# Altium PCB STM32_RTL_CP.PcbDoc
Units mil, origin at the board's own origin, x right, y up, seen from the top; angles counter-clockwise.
Board outline 3165.87 x 3946.73 mil, 2 copper layers (Top Layer, Bottom Layer); 80 components, 87 nets, 425 pads, 181 vias.
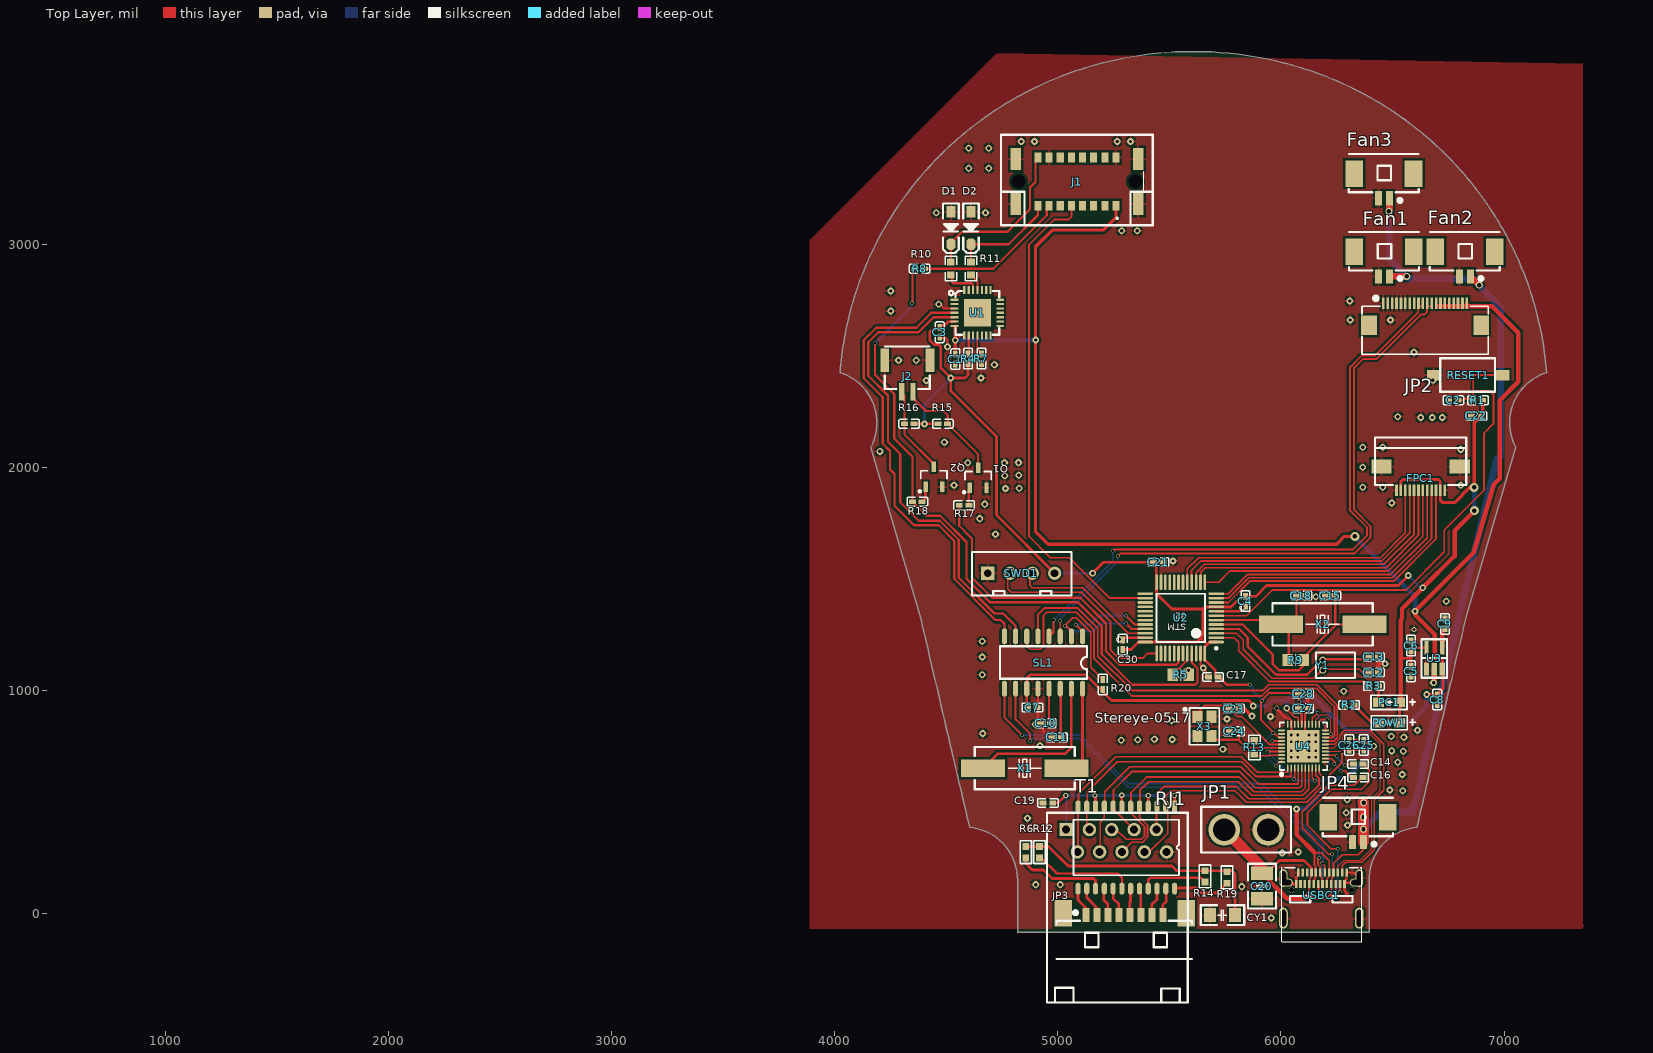
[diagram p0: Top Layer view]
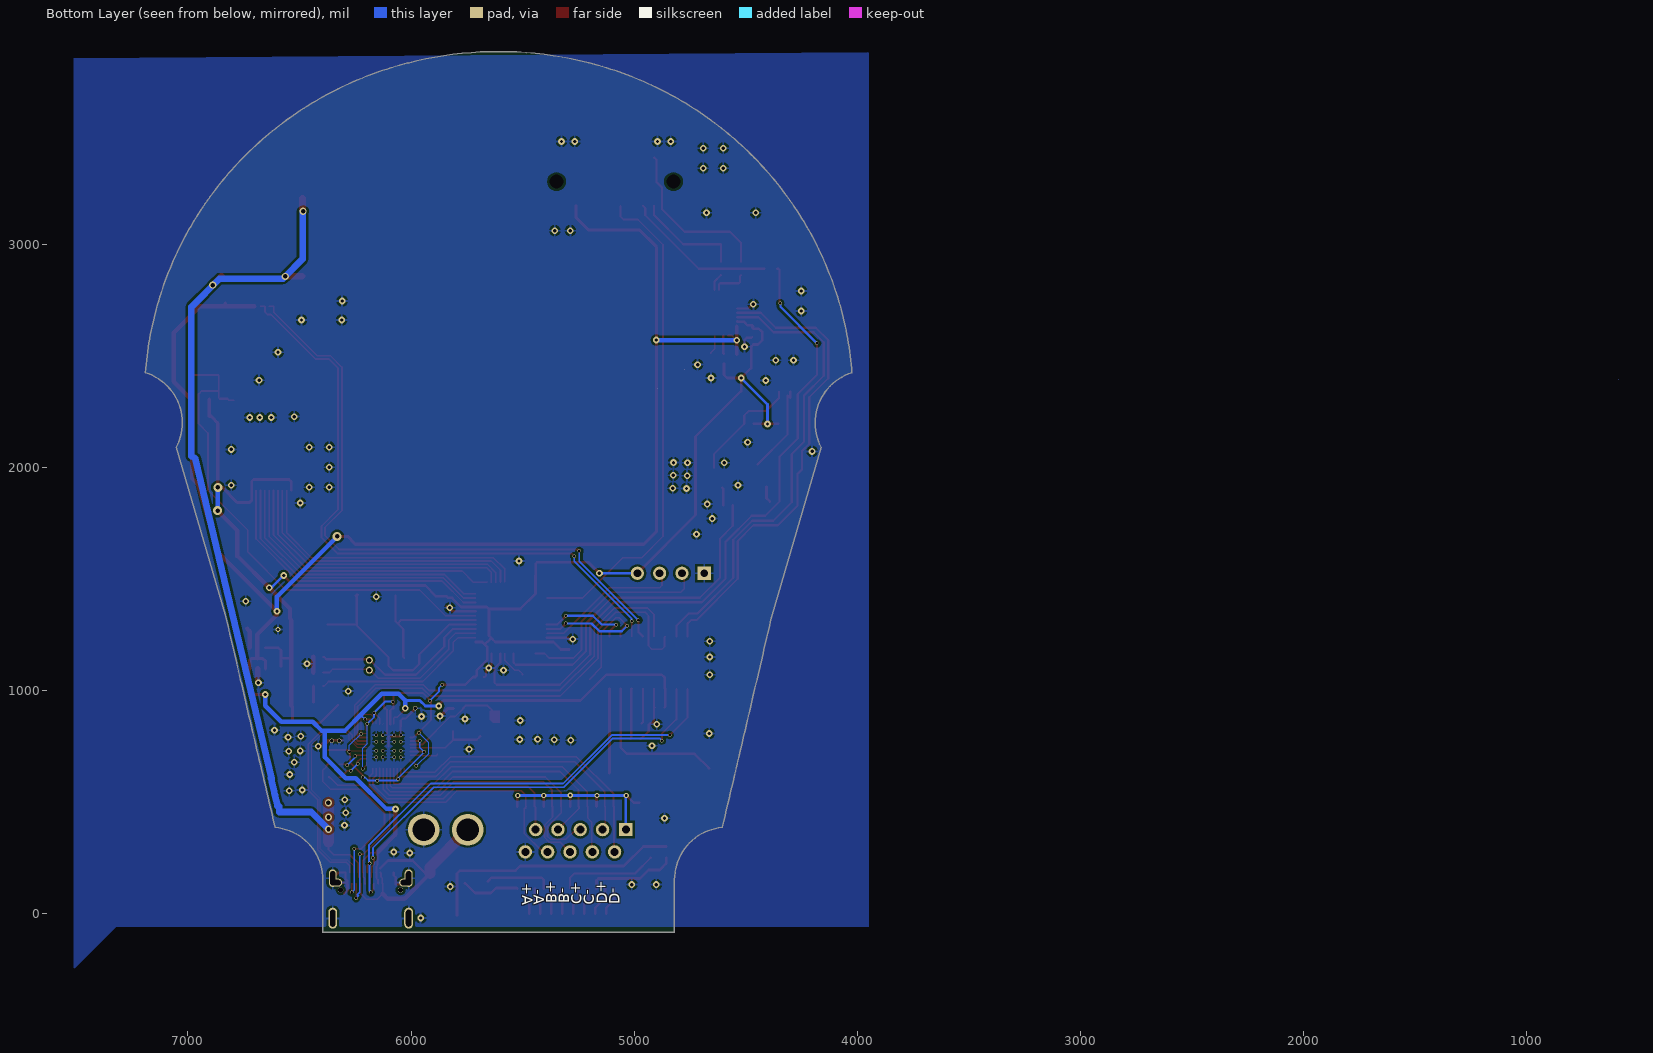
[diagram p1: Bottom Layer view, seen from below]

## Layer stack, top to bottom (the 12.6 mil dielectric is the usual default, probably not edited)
Top Solder: solder mask 0.4, Solder Resist, Dk 3.5
Top Layer: signal copper 1.4
Dielectric 1: dielectric 12.6, FR-4, Dk 4.8
Bottom Layer: signal copper 1.4
Bottom Solder: solder mask 0.4, Solder Resist, Dk 3.5

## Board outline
890 vertices, not listed, extent 4024.3,-84.27 7190.16,3862.46
cut-out: 4894,2351
cut-out: 4774,2440

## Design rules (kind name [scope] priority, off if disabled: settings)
Clearance [All] p1: gap=5 ignorepadtopadclearanceinfootprint=FALSE except(10: Arc-Fill Arc-Poly Arc-Region Track-Fill Track-Poly Track-Region SMDPad-Fill SMDPad-Poly SMDPad-Region THPad-Fill THPad-Poly THPad-Region Via-Fill Via-Poly Via-Region Fill-Fill Fill-Poly Fill-Region Poly-Poly Poly-Region Region-Region)
DiffPairsRouting [All] p1: maxlimit=50 minlimit=5 mostfreqgap=5 toplayer_minwidth=5 toplayer_maxwidth=20 toplayer_prefwidth=8 bottomlayer_minwidth=5 bottomlayer_maxwidth=20 bottomlayer_prefwidth=8 maxuncoupledlength=500
PolygonConnect [All] p1: connectstyle=Relief reliefconductorwidth=10 reliefentries=4 polygonreliefangle="90 Angle" airgapwidth=10
RoutingVias [All] p1: holewidth=11.81 width=15.75 viastyle="Through Hole" minholewidth=11.81 minwidth=15.75 maxholewidth=28 maxwidth=50
SolderMaskExpansion [All] p1: expansion=4
Width All [All] p1: maxlimit=100 minlimit=5 preferedwidth=10 minimp=50.000000 maximp=50.000000 favimp=50.000000
Width VCC [InNet('5V')] p2: maxlimit=100 minlimit=5 preferedwidth=10
29 further rules are at their usual default settings.

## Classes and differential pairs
differential pair SSTX: +SSTX_P -SSTX_N
differential pair MDI3: +MDI3_P -MDI3_N
differential pair MDI2: +MDI2_P -MDI2_N
differential pair MDI1: +MDI1_P -MDI1_N
differential pair MDI0: +MDI0_P -MDI0_N
differential pair SSRX: +SSRX_P -SSRX_N
differential pair USB3-D: +USB3-D_P -USB3-D_N
differential pair D3: +D3_P -D3_N
differential pair D2: +D2_P -D2_N
differential pair D1: +D1_P -D1_N

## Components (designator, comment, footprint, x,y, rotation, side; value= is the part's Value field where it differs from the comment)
C1 "10UF" C0402_NEW 4541,2485 r270 top
C2 "105" C0402_NEW 6772.54,2300.36 r0 top
C3 "10UF" C0402_NEW 4471,2605 r90 top
C4 "104" C0402_NEW 5841,1400 r90 top
C5 "106" C0402_NEW 6583,1086 r270 top
C6 "104" C0402_NEW 6583,1201 r270 top
C7 "104" C0402_NEW 4886,923 r180 top
C8 "105" C0402_NEW 6700,959 r90 top
C9 "223" C0402_NEW 6735,1298 r270 top
C10 "10uF" C0402_NEW 4946,853 r0 top
C11 "10uF" C0402_NEW 4996,790.08 r0 top
C12 "22P" C0402_NEW 6416,1080 r0 top
C13 "22P" C0402_NEW 6416,1150 r0 top
C14 "0.1uF" C0402_NEW 6346,670 r0 top
C15 "22P" C0402_NEW 6221,1425 r180 top
C16 "0.1uF" C0402_NEW 6346,610 r0 top
C17 "10nf" C0402_NEW 5696,1060 r0 top
C18 "22P" C0402_NEW 6091,1425 r0 top
C19 "0.1UF" C0402_NEW 4956,496 r180 top
C20 "104" "C 1210_L" 5915,123 r90 top
C21 "105" C0402_NEW 5451,1575 r180 top
C22 "105" C0402_NEW 6876,2230 r0 top
C23 "30PF" C0402_NEW 5789,919 r0 top
C24 "30PF" C0402_NEW 5790,817 r0 top
C25 "10nf" C0402_NEW 6371,755 r270 top
C26 "0.1uf" C0402_NEW 6306,755 r270 top
C27 "10nf" C0402_NEW 6099.54,920 r180 top
C28 "0.1uf" C0402_NEW 6099.54,985 r180 top
C30 "10nf" C0402_NEW 5291,1205 r270 top
CY1 "10nF/1KV" "C 1206_L" 5737,-7 r0 top
D1 "FFM107" SOD-123F 4521,3072.17 r270 top
D2 "FFM107" SOD-123F 4611,3072.17 r270 top
Fan1 "HDR-1X2" "MX 1.25-WS-2P" 6462,2966 r180 top
Fan2 "HDR-1X2" "MX 1.25-WS-2P" 6824,2966 r180 top
Fan3 "HDR-1X2" "MX 1.25-WS-2P" 6461,3316 r180 top
FPC1 "FPC-12P" FPC-0.5MM-12P 6626,1950 r0 top
J1 "254587" MH-16 5086,3280 r180 top
J2 "GH1.25_2P" GH1.25_2P 4326,2437.99 r180 top
JP1 "HDR-1X2" XT30 5844.43,376 r0 top
JP2 "HDR-1X20" "FPC0.5 2H-WS-20P" 6646,2636.95 r0 top
JP3 "HDR-1X8" "MX 1.25-WS-8P" 5300,-116 r0 top
JP4 "HDR-1X2" "MX 1.25-WS-2P" 6345,431 r180 top
PC1 "LEDgreen" LED 6484.24,946.5 r0 top
POW1 "LEDred" LED 6485,855 r0 top
Q1 "SI2302" SOT23-3N 4643,1953 r0 top
Q2 "SI2302" SOT23-3N 4445,1957 r0 top
R1 "10K,0603" C0402_NEW 6882.54,2300.36 r0 top
R2 "510R,0603" C0402_NEW 6306,935 r180 top
R3 "510R,0603" C0402_NEW 6416,1020 r180 top
R4 "5k" C0402_NEW 4598,2486.54 r270 top
R5 "10K,0603" 6-0805_N 5551,1070 r0 top
R6 "1K" "R 0603_L" 4857,275 r270 top
R7 "5k" C0402_NEW 4658,2486.54 r270 top
R8 "5k" C0402_NEW 4381,2890 r180 top
R9 "1M" 6-0805_N 6066,1136.13 r0 top
R10 "68R,0603" R0603_NEW 4521,2890.35 r270 top
R11 "68R,0603" R0603_NEW 4611,2890.35 r270 top
R12 "1K" "R 0603_L" 4918,275 r270 top
R13 "2.49k" R0603_NEW 5881,745 r90 top
R14 "1K" "R 0603_L" 5660,167 r270 top
R15 "510R,0603" C0402_NEW 4485,2195 r180 top
R16 "510R,0603" C0402_NEW 4334,2195 r0 top
R17 "68R,0603" C0402_NEW 4580,1830 r180 top
R18 "68R,0603" C0402_NEW 4371,1846 r180 top
R19 "1K" "R 0603_L" 5758,162 r270 top
R20 "5k" C0402_NEW 5202,1026.54 r90 top
RESET1 "SW-PB" Key 6684,2413 r180 top
RJ1 "HR911130A" "RJ45-TH_HR911130A - duplicate" 5267,104 r180 top
SL1 "SL2.1A" SOP-16_L10.0-W3.9-P1.27-LS6.0-BL 4936,1125 r180 top
SWD1 "SWD" HDR1X4H 4686,1525 r0 top
T1 "SG24002g" SG24002 5523.48,480 r270 top
U1 "CP2102" CP2102-28G 4640,2692 r0 top
U2 "STM32F103C8T6" STM32-48P 5551,1325 r180 top
U3 "RT9193-33GB" SOT-23-5 6687.57,1143.76 r0 top
U4 "RTL8153B-VB-CG" QFN-40_L5.0-W5.0-P0.40-BL-EP3.7 6101,750 r0 top
USBC1 "TypeC SMD" USB-C-SMD_MC-312D-C 6181,39.69 r0 top
X1 "12MHz" "OSC HC-49SMD" 4852,652 r180 top
X2 "8MHz" "OSC HC-49SMD" 6187.01,1296 r0 top
X3 "25MHz" OSC-SMD_4P-L3.2-W2.5-BL 5657,839 r90 top
Y1 "32.768K" XLAT-32 6186.98,1135.5 r270 top

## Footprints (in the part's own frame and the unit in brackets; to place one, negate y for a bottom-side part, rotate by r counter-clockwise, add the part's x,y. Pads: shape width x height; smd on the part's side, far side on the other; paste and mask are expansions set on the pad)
6-0805_N [mm] "Chip Resistor, Body 2.0x1.2mm, IPC Medium Density"
  rect 1.2x1.4 smd: 1(-0.9,0) 2(0.9,0)
  silkscreen extent 0,-0.6 0,0.6, body extent -1.07,-0.7 1.07,0.7, height 0.7
C0402_NEW [mm]
  rect 0.79x0.54 smd: 1(-0.545,0) 2(0.545,0)
  silkscreen extent -1.17,-0.5 1.17,0.5
"C 1206_L" [mil] "无极性贴片电容"
  rect 55x62 smd: 1(-55.12,0) 2(57.09,0)
  silkscreen extent -96,-44 98,44, body extent -63,-32 63,32, height 48
"C 1210_L" [mil] "无极性贴片电容                                淘宝ID:黄晶宝石"
  rect 60x100 smd: 1(-57.09,0) 2(57.09,0)
  silkscreen extent -100,-63 100,63, body extent -63,-51 63,51, height 60
CP2102-28G [mil]
  rect 35.4x10 smd: 1(-102,59) 2(-102,39) 3(-102,20) 4(-102,0) 5(-102,-20) 6(-102,-39) 7(-102,-59) 15(102,-59) 16(102,-39) 17(102,-20) 18(102,0) 19(102,20) 20(102,39) 21(102,59)
  rect 10x35.4 smd: 8(-59,-102) 9(-39,-102) 10(-20,-102) 11(0,-102) 12(20,-102) 13(39,-102) 14(59,-102) 22(59,102) 23(39,102) 24(20,102) 25(0,102) 26(-20,102) 27(-39,102) 28(-59,102)
  rect 122x122 smd: 29(0,0)
  silkscreen extent -128,-98 98,99
"FPC0.5 2H-WS-20P" [mm] "长：14.2mm，宽：5.2mm，高：2mm  淘宝ID:黄晶宝石   店铺网址:https://shop463601444.taobao.com"
  rect 1.8x2.2 smd: 0(-6.4,0) 0(6.4,0)
  rect 0.3x1.3 smd: 1(-4.75,2.497) 2(-4.25,2.497) 3(-3.75,2.497) 4(-3.25,2.497) 5(-2.75,2.497) 6(-2.25,2.497) 7(-1.75,2.497) 8(-1.25,2.497) 9(-0.75,2.497) 10(-0.25,2.497) 11(0.25,2.497) 12(0.75,2.497) 13(1.25,2.497) 14(1.75,2.497) 15(2.25,2.497) 16(2.75,2.497) 17(3.25,2.497) 18(3.75,2.497) 19(4.25,2.497) 20(4.75,2.497)
  silkscreen extent -7.18,-3.3 7.18,3.23, body extent -7.1,-3.15 7.1,2.85, height 2
FPC-0.5MM-12P [mm]
  rect 0.3x1.3 smd: 1(-2.751,-1.341) 2(-2.252,-1.341) 3(-1.751,-1.341) 4(-1.251,-1.341) 5(-0.751,-1.341) 6(-0.25,-1.341) 7(0.25,-1.341) 8(0.749,-1.341) 9(1.248,-1.341) 10(1.749,-1.341) 11(2.249,-1.341) 12(2.75,-1.341)
  rect 2.286x1.6 smd: 13(4.45,1.34) 14(-4.45,1.34)
  silkscreen extent -5.18,-0.76 5.18,4.67
GH1.25_2P [mm]
  rect 0.6x2 smd: 1(-0.635,2.54) 2(0.635,2.54)
  rect 1x2.7 smd: 3(2.585,-1.041) 4(-2.565,-1.041)
  silkscreen extent -2.55,-2.62 2.57,2.21
HDR1X4H [mm] "Connector; Header; 4 Position; Right Angle"
  rect 1.5x1.5 hole 0.9: 1(0,0)
  round 1.5 hole 0.9: 2(2.54,0) 3(5.08,0) 4(7.62,0)
  silkscreen extent -1.78,-2.54 9.52,2.41
Key [mil]
  rect 59.06x47.24 smd: 1(0,0) 2(-310,0)
  silkscreen extent -275,-75 -30,75
LED [mil]
  rect 49x43 smd: 1(46.26,0) 2(-46.26,0)
  silkscreen extent -81,-31 118,31
MH-16 [mm]
  rect 0.8x1.1 smd: A1(4.445,-2.75) A2(3.175,-2.75) A3(1.905,-2.75) A4(0.635,-2.75) A5(-0.635,-2.75) A6(-1.905,-2.75) A7(-3.175,-2.75) A8(-4.445,-2.75) B1(4.445,2.75) B2(3.175,2.75) B3(1.905,2.75) B4(0.635,2.75) B5(-0.635,2.75) B6(-1.905,2.75) B7(-3.175,2.75) B8(-4.445,2.75)
  round 0.8 hole 1.6 unplated: MH1(-6.655,0) MH2(6.655,0)
  rect 1.2x2.5 smd: MP1(-6.955,2.55) MP2(-6.955,-2.55) MP3(6.955,2.55) MP4(6.955,-2.55)
  silkscreen extent -8.64,-5.33 8.64,4.95, body extent -7.62,-3.5 7.62,3.5, height 6.7
"MX 1.25-WS-2P" [mm] "长：7.65mm，宽：4.2mm，高：3.4mm"
  rect 2x3 smd: 0(-3.382,0) 0(3.382,0)
  rect 0.8x1.6 smd: 1(-0.639,2.811) 2(0.611,2.811)
  silkscreen extent -3.98,-2.23 4,3.25, body extent -3.83,-2.1 3.83,3.09, height 3.4
"MX 1.25-WS-8P" [mm] "长：15.15mm，宽：4.2mm，高：3.4mm"
  rect 2x3 smd: 0(-7,3) 0(7,3)
  rect 0.8x1.6 smd: 1(-4.389,2.811) 2(-3.139,2.811) 3(-1.889,2.811) 4(-0.639,2.811) 5(0.611,2.811) 6(1.861,2.811) 7(3.111,2.811) 8(4.361,2.811)
  silkscreen extent -7.77,-2.23 7.67,3.25, body extent -7.57,-2.1 7.57,3.09, height 3.4
"OSC HC-49SMD" [mm] "封装库来自淘宝卖家 ID：黄晶宝石"
  rect 5x2 smd: 1(-4.75,0) 2(4.75,0)
  silkscreen extent -5.7,-2.4 5.7,2.4, body extent -6.5,-2.32 6.5,2.33, height 4.63
OSC-SMD_4P-L3.2-W2.5-BL [mm]
  rect 1.4x1.15 smd: 1(1.059,0.8) 2(-1.1,0.8) 3(-1.1,-0.8) 4(1.1,-0.8)
  Top Layer region: 1.8,0.225 0.762,0.225 0.4,0.604 0.4,1.375 1.8,1.375
  silkscreen extent -2.1,-1.7 2.1,2.35
QFN-40_L5.0-W5.0-P0.40-BL-EP3.7 [mm]
  oval 0.2x0.8 smd: 1(-1.8,-2.499) 2(-1.4,-2.499) 3(-1,-2.499) 4(-0.6,-2.499) 5(-0.2,-2.499) 6(0.2,-2.499) 7(0.6,-2.499) 8(1,-2.499) 9(1.4,-2.499) 10(1.8,-2.499) 21(1.8,2.499) 22(1.4,2.499) 23(1,2.499) 24(0.6,2.499) 25(0.2,2.499) 26(-0.2,2.499) 27(-0.6,2.499) 28(-1,2.499) 29(-1.4,2.499) 30(-1.8,2.499)
  oval 0.8x0.2 smd: 11(2.499,-1.8) 12(2.499,-1.4) 13(2.499,-1) 14(2.499,-0.6) 15(2.499,-0.2) 16(2.499,0.2) 17(2.499,0.6) 18(2.499,1) 19(2.499,1.4) 20(2.499,1.8) 31(-2.499,1.8) 32(-2.499,1.4) 33(-2.499,1) 34(-2.499,0.6) 35(-2.499,0.2) 36(-2.499,-0.2) 37(-2.499,-0.6) 38(-2.499,-1) 39(-2.499,-1.4) 40(-2.499,-1.8)
  rect 3.7x3.7 smd: 41(0,0)
  silkscreen extent -2.7,-3.35 2.7,2.7
R0603_NEW [mil]
  rect 31.75x34.02 smd: 1(-29.65,0) 2(29.66,0)
  silkscreen extent -55,-26 55,26
"R 0603_L" [mil] "1/10W贴片电阻                 淘宝ID:黄晶宝石"
  rect 30x30 smd: 1(-25.59,0) 2(25.59,0)
  silkscreen extent -51,-26 51,26, body extent -31,-16 32,16, height 16
"RJ45-TH_HR911130A - duplicate" [mil]
  rect 60x60 hole 35.83: P1(229.63,-272.62)
  round 60 hole 35.83: P2(179.1,-172.38) P3(125.2,-272.38) P4(79.1,-172.38) P5(25.2,-272.38) P6(-20.9,-172.38) P7(-74.8,-272.38) P8(-120.9,-172.38) P9(-174.8,-272.38) P10(-220.9,-172.38)
  silkscreen extent -315,-347 315,503
SG24002 [mm]
  rect 1.35x0.6 smd: 1(0,0)
  oval 1.35x0.6 smd: 2(0,-1) 3(0,-2) 4(0,-3) 5(0,-4) 6(0,-5) 7(0,-6) 8(0,-7) 9(0,-8) 10(0,-9) 11(0,-10) 12(0,-11) 13(9.35,-11) 14(9.35,-10) 15(9.35,-9) 16(9.35,-8) 17(9.35,-7) 18(9.35,-6) 19(9.35,-5) 20(9.35,-4) 21(9.35,-3) 22(9.35,-2) 23(9.35,-1) 24(9.35,0)
  silkscreen extent 1.51,-11.5 7.84,0.5
SOD-123F [mm] "2.7x1.6X1.1mm（长宽高，不包括引脚）"
  rect 1.3x1 smd: 1(-1.85,0)
  oct 1.3x1 smd: 2(1.85,0)
  silkscreen extent -2.79,-0.89 2.84,0.89, body extent -1.9,-0.8 1.9,0.8, height 1.15
SOP-16_L10.0-W3.9-P1.27-LS6.0-BL [mm]
  oval 0.6x1.8 smd: 1(-4.445,-2.972) 2(-3.175,-2.972) 3(-1.905,-2.972) 4(-0.635,-2.972) 5(0.635,-2.972) 6(1.905,-2.972) 7(3.175,-2.972) 8(4.445,-2.972) 9(4.445,2.972) 10(3.175,2.972) 11(1.905,2.972) 12(0.635,2.972) 13(-0.635,2.972) 14(-1.905,2.972) 15(-3.175,2.972) 16(-4.445,2.972)
  silkscreen extent -4.95,-1.85 4.95,1.85
SOT23-3N [mm] "3x1.3x1mm(长宽高)    封装库来自淘宝卖家 ID：黄晶宝石"
  rect 0.5x1.2 smd: 1(-0.95,-1.143) 2(0.95,-1.143) 3(0,1.143)
  silkscreen extent -1.72,-1.78 1.5,0.7, body extent -1.5,-1.2 1.5,1.2, height 1.05
SOT-23-5 [mm]
  rect 0.6x1.5 smd: 1(-0.9,-1.2) 2(0,-1.2)
  rect 0.63x1.5 smd: 3(0.9,-1.2)
  rect 0.5x1.5 smd: 4(0.9,1.2) 5(-0.9,1.2)
  silkscreen extent -1.47,-2.21 1.43,2.18
STM32-48P [mm]
  oval 1.8x0.3 smd: 1(-4.05,2.75) 2(-4.05,2.25) 3(-4.05,1.75) 4(-4.05,1.25) 5(-4.05,0.75) 6(-4.05,0.25) 7(-4.05,-0.25) 8(-4.05,-0.75) 9(-4.05,-1.25) 10(-4.05,-1.75) 11(-4.05,-2.25) 12(-4.05,-2.75) 25(4.05,-2.75) 26(4.05,-2.25) 27(4.05,-1.75) 28(4.05,-1.25) 29(4.05,-0.75) 30(4.05,-0.25) 31(4.05,0.25) 32(4.05,0.75) 33(4.05,1.25) 34(4.05,1.75) 35(4.05,2.25) 36(4.05,2.75)
  oval 0.3x1.8 smd: 13(-2.75,-4.05) 14(-2.25,-4.05) 15(-1.75,-4.05) 16(-1.25,-4.05) 17(-0.75,-4.05) 18(-0.25,-4.05) 19(0.25,-4.05) 20(0.75,-4.05) 21(1.25,-4.05) 22(1.75,-4.05) 23(2.25,-4.05) 24(2.75,-4.05) 37(2.75,4.05) 38(2.25,4.05) 39(1.75,4.05) 40(1.25,4.05) 41(0.75,4.05) 42(0.25,4.05) 43(-0.25,4.05) 44(-0.75,4.05) 45(-1.25,4.05) 46(-1.75,4.05) 47(-2.25,4.05) 48(-2.75,4.05)
  silkscreen extent -4.18,-2.75 2.75,3.57, body extent -3.5,-3.5 3.5,3.5, height 1.6
USB-C-SMD_MC-312D-C [mm]
  oval 0.9x2 hole 0.6 slot 1.6 at 90 deg: 1(-4.32,3.018) 2(4.32,3.018)
  oval 1.5x0.9 hole 0.6 slot 1.2 at 0 deg: 1(-4,2.518) 2(4,2.518)
  oval 1x2.4 hole 0.6 slot 1.9 at 90 deg: 3(4.32,-1.532) 4(-4.32,-1.532)
  rect 0.3x0.95 smd: A1(-2.62,3.668) A2(-2.12,3.668) A3(-1.62,3.668) A4(-1.12,3.668) A5(-0.62,3.668) A6(-0.12,3.668) A7(0.38,3.668) A8(0.88,3.668) A9(1.38,3.668) A10(1.88,3.668) A11(2.38,3.668) A12(2.88,3.668) B1(2.63,2.368) B2(2.13,2.368) B3(1.63,2.368) B4(1.13,2.368) B5(0.63,2.368) B6(0.13,2.368) B7(-0.37,2.368) B8(-0.87,2.368) B9(-1.37,2.368) B10(-1.87,2.368) B11(-2.37,2.368) B12(-2.87,2.368)
  round 0.6 hole 0.6 unplated: ""(-3.4,1.668) ""(3.4,1.668)
  silkscreen extent -4.57,-4.2 4.57,4.18
XLAT-32 [mm]
  round 0.8 hole 0.5: 0(0,0) 1(1.143,0)
  silkscreen extent -0.89,-0.76 2.03,3.68
XT30 [mm]
  round 3.6 hole 2.6: 1(-2.5,0) 2(2.5,0)
  silkscreen extent -5.12,-2.59 5.09,2.62

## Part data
C1 C3: library part 47uf, BOM_Manufacturer Part=?
C2 C4 C5 C6 C7 C8 C9 C12 C13 C15 C18 C20 C21 C22: BOM_Manufacturer=YAGEO, BOM_Manufacturer Part=CC0603KRX7R9BB104
C10 C11: BOM_JLCPCB Part Class="Extended Part", BOM_Manufacturer=SAMSUNG, BOM_Manufacturer Part=CL10A106MP8NNNC
CY1: library part CY, "安规Y电容"
D1 D2: "快恢复整流二极管"
Fan1 Fan2 Fan3 JP1 JP4: library part "Header 2", "2P接插件"
FPC1: BOM_Manufacturer=JUSHUO, BOM_Manufacturer Part=AFC01-S12FCA-00
J1: "Connector", Manufacturer_Name=ERNI, Mouser Part Number=305-254587
JP2: library part "Header 20", "20P接插件"
JP3: library part "Header 8", "8P接插件"
PC1 POW1: library part LED
Q1 Q2: "N沟道场效应管"
R1 R5: BOM_Manufacturer=UniOhm, BOM_Manufacturer Part=060300J0103T5E
R2 R3 R15 R16: BOM_Manufacturer=UniOhm, BOM_Manufacturer Part=0603WAJ0511T5E
R4 R7 R8 U1: BOM_Manufacturer Part=?
R6 R12 R14 R19: library part R, "贴片电阻"
R9: library part 1M0603, BOM_Manufacturer="Uniroyal Elec", BOM_Manufacturer Part=0603WAF1054T5E
R10 R11 R17 R18 R20: library part 510R,0603, BOM_Manufacturer=UniOhm, BOM_Manufacturer Part=0603WAJ0511T5E
RJ1: BOM_Manufacturer=HANRUN
SL1: BOM_LCSC Assembly=Yes, BOM_Manufacturer=CoreChips
SWD1: BOM_Manufacturer=Ckmtw, BOM_Manufacturer Part="210S-1*4P L{}11.6MMGold-plated black"
U3: BOM_Manufacturer=RICHTEK, ICA_PARTNUM=$$2191094$$RT9193-15CU5, Part Number=TMP-13
U4: BOM_JLCPCB Part Class="Extended Part", BOM_Manufacturer=REALTEK(瑞昱)
X1: BOM_JLCPCB Part Class="Extended Part", BOM_Manufacturer=YXC, BOM_Manufacturer Part=X49SD12MSD2SC
X2: BOM_Manufacturer="ZheJiang East Crystal Elec", BOM_Manufacturer Part=B08000J065
X3: BOM_LCSC Assembly=Yes, BOM_Manufacturer="Zhejiang Abel Elec", BOM_Manufacturer Part=SMD-3225_4P25MHZ12PF10PPM-40~+85℃
Y1: library part XLAT-32, BOM_Manufacturer=KDS, BOM_Manufacturer Part="DST310S 32.768KHz"

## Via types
v1: diameter 30, hole 15, Top Layer to Bottom Layer, 108 vias
v2: diameter 15.75, hole 11.81, Top Layer to Bottom Layer, 55 vias
v3: diameter 32, hole 20, Top Layer to Bottom Layer, 6 vias
v4: diameter 24, hole 12, Top Layer to Bottom Layer, 6 vias
v5: diameter 40, hole 20, Top Layer to Bottom Layer, 3 vias
v6: diameter 20, hole 15.75, Top Layer to Bottom Layer, 3 vias

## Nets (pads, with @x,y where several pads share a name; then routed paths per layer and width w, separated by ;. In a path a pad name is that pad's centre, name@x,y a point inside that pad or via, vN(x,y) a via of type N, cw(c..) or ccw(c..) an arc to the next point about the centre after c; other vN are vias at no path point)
1V0: C25.2 C26.2 U4.3 U4.8 U4.14 U4.19 U4.22 U4.34 U4.37 | length 1229.7
  Top Layer w5: U4.22 6156.67,848.95 6156.67,869.27 6172.02,884.63 6172.37,884.63 6177.74,890 6211,890 6222.65,878.35 v2(6222.65,806.65) 6200.93,806.65 U4.19 ; U4.14 v2@6276,726.38
  Top Layer w8: v2(5941,724.25) 5943.1,724.25 5945.22,726.38 U4.37 ; v2(5961,775) 5962.31,773.69 6002.54,773.69 U4.34 ; v2(6058,602) 6061.63,605.63 U4.3 ; U4.8 6140.43,651.54 6140.43,607.66 6151,597.1 v2(6151,595) ; v2(6216,610) 6216,620 6274.13,678.13 v2@6274.13,723.13 ; v2(6276,725) 6276,726.38 6276,730 6279.54,733.54 C26.2 C25.2
  Bottom Layer w5: v2(6222.65,806.65) 6276,753.3 v2(6276,725)
  Bottom Layer w8: v2(5961,775) 5961,744.25 v2(5941,724.25) 6058.4,606.86 6058.4,597 6193,597 6206,610 v2(6216,610)
3V3: C3.2 C4.2 C5.1 C6.2 C17.2 C21.2 C22.2 C27.2 C28.2 C30.2 FPC1.2 FPC1.11 PC1.1 POW1.1 R1.2 R4.2 R15.2 R16.2 SWD1.4 U1.6 U2.1 U2.9 U2.24 U2.36 U2.48 U3.5 U4.11 U4.20 U4.23 U4.26 U4.33 U4.39 U4.40 | length 8491.5
  Top Layer w5: v2@5976,660 v2(5976,662.17) 5976,664.35 5990.79,679.13 U4.40 U4.39 ; U4.11 6199.4,666.6 v2(6216,650)
  Top Layer w8: U4.33 5990.91,789.37 5988.1,792.18 5985.43,792.18 5911,866.61 5911,953.23 5946.88,989.12 6073.97,989.12 C28.2 ; U4.23 6140.43,848.46 6140.43,874.43 v2(6166,900) ; v2(6196,850) 6199.4,846.6 U4.20
  Top Layer w10: C28.2 C27.2 6083.01,920 6093.13,909.88 U4.26
  Top Layer w12: R16.2 R15.2 ; 4425.97,2595.03 4425.97,2604.97 4442.37,2621.37 4466.37,2621.37 4471,2626 C3.2 ; 4426,2595 4426,2570 4446,2550 4466,2550 4476,2540 4476,2445 v1(4521,2400) ; C3.2@4466,2626.46 4466,2631.38 4470.63,2636.01 4492.01,2636.01 4508,2652 4537,2652 U1.6 ; R4.2 4598,2414.03 4583.97,2400 v1(4521,2400) ; SWD1.4 4725,1786 4725,2137 4521,2341 v1(4521,2400) ; v1(5156,1525) 5206,1575 C21.2 5434.47,1575 5441.1,1568.37 5441.1,1516.64 5442.73,1515.01 U2.24 5442.73,1433.27 5511,1365 5651,1365 ; C30.2 5328.83,1183.54 5362.02,1216.73 U2.36 5622.47,1216.73 5636.74,1231 ; U2.1@5679.89,1216.73 U2.1@5680.92,1216.73 ; U2.1 U2.1@5680.92,1216.73 ; v2@5856,1025 5757.38,1025 5722.38,1060 C17.2 5712.54,1060 5705.91,1066.63 5705.91,1089.39 5659.27,1136.02 U2.48 5659.27,1195.08 5670.09,1205.91 ; POW1.1 6531.26,929 PC1.1@6537.26,935 ; 6537.26,1144 6537.76,1143.5 6583,1143.5 ; FPC1.2 6537.44,1897.32 6537.44,1936.44 6546,1945 6706,1945 6714.45,1936.55 6714.45,1897.32 FPC1.11 6714.55,1851.45 6716,1850 ; v1(6571,1515) 6526,1470 5936,1470 5887.46,1421.46 C4.2 5834.54,1415 5816,1415 5775.21,1374.21 U2.9 5660.21,1374.21 5651,1365 ; C5.1 6583,1143.5 ; U3.5 6594.46,1191 C6.2 6583,1143.5 ; 5636.74,1231 5651,1245.26 5651,1365 ; 5636.74,1231 5645,1231 5670.09,1205.91 ; 5670.09,1205.91 U2.1@5680.92,1216.73
  Top Layer w15: 6716,1850 6724,1842 6778,1842 6846,1910 v5(6866,1910) 6866,2198.54 6874.33,2206.87 6875.27,2206.87 6882.59,2214.19 6882.59,2215.14 6895.49,2228.03 6904,2228.03 R1.2 R1.2@6904,2305
  Top Layer w20: PC1.1@6537.91,934.35 6537.26,935 6537.26,1144 6537.26,1315 6542.5,1320.24 6542.5,1366.5 v1(6636,1460) 6778,1602 6778,1716 6867,1805 v5(6867,1806)
  Bottom Layer w5: v2(5966,810) 5921,765 5921,717.17 v2(5976,662.17) ; v2(6196,850) 6196,760 6216,740 v2(6216,650)
  Bottom Layer w8: v2(5861,1025) 5875.05,1010.95 5875.05,994.18 v2(5916,953.23) ; v2(6166,900) 6166,880 v2(6196,850)
  Bottom Layer w10: v2(6081,950) 6116,950 v2(6166,900)
  Bottom Layer w12: v1(4403,2194) 4403,2282 v1(4521,2400) ; SWD1.4 v1(5156,1525) ; v1(6571,1515) 6622.56,1463.44 6632.56,1463.44 v1(6636,1460)
  Bottom Layer w20: v5@6861,1815 v5@6866,1820 ; v5(6866,1910) v5@6866,1820 ; v5(6867,1806) 6867,1812 6868,1813 6866,1815 v5@6866,1820
5V: C1.1 C7.2 C8.2 J1.B8 JP2.13 JP2.14 JP2.15 JP2.16 JP2.17 JP2.18 JP2.19 JP2.20 R20.1 SL1.11 U1.7 U1.8 U3.1 U3.3 U4.21 U4.27 USBC1.A5 USBC1.A8 USBC1.B5 USBC1.B8 | length 10111
  Top Layer w8: U1.7 4540,2633 U1.7@4541,2632 ; v1(4541,2569.23) 4561.77,2590 U1.8 ; C7.2@4861,926.54 C7.2 ; v1(6026,920) 6026,915 6061,880 6073.53,880 6077.38,876.15 U4.27 ; 6146,273 6151,273 ; USBC1.B8 6148.66,134.82 6148.66,152.47 6154.68,158.5 USBC1.A5@6154.68,186 ; USBC1.A5 USBC1.A5@6154.68,186 ; U4.21 6171.87,860.09 6181.78,870 v2(6206,870) ; USBC1.B5 6207.71,134.82 6207.71,158.51 6213.74,164.54 6213.74,182.19 USBC1.A8 6216,184.44 6216,237 6180,273 6151,273 ; 6151,273 6151,216.3 6154.68,212.62 USBC1.A5@6154.68,186
  Top Layer w12: C7.2@4861,926.54 SL1.11 4863.22,1010.22 4863.22,1057.22 4876,1070 5126,1070 5241,955 5856,955 v1@5876,935
  Top Layer w15: C1.1 v1(4541,2569.23) U1.7@4541,2632 ; J1.B8 5261,3120 5204,3063 4976,3063 4900,2987 4900,2570 4900,1712.72 4957.25,1655.46 6249.08,1655.46 6283.62,1690 v5(6331,1690) ; U3.1 6652.13,1130.13 6665,1143 6690,1143 6715,1143 6723,1135 U3.3 6726,1093.51 6726,1006.46 C8.2 6698.46,982 v1(6653,982) ; 6824,2721 6833.01,2730.01 JP2.20
  Top Layer w20: v1(6070,469) 6070,354 6151,273 ; 6690,1143 6689,1144 6689,1251 6601,1339 v1(6601,1355) 6864.1,1618.1 6953.1,1922.45 6979.65,1949 6980.27,1949 6980.27,2299.27 7064,2383 7064,2603 6946,2721 6824,2721 6773.95,2721 6702,2721
  Bottom Layer w8: v2(6206,870) 6221,885 6221,895
  Bottom Layer w12: v1(5876,930) 5936,930 5961,955 6026,955
  Bottom Layer w20: v1(4541,2569.23) 4541.39,2569.61 4900.61,2569.61 v1(4901,2570) ; v1(6026,920) 6026,955 6056,985 6131,985 6221,895 6296,820 6386,820 ; v1(6070,469) 6110,469 6247.91,606.91 6292.91,606.91 6386,700 6386,820 ; v5(6331,1690) 6601,1420 v1(6601,1355) ; v1(6653,982) 6653,931 6582,860 6441,860 6401,820 6386,820
BOOT0: R5.1 U2.44 | length 140
  Top Layer w8: R5.1@5500.57,1070 5500.57,1073.94 5516.63,1090 5535.9,1090 5575.75,1129.85 5575.75,1130.21 5580.53,1134.99 U2.44
BOOT1: U2.20
D1_N: SL1.7 U1.5 | length 2103.3
  Top Layer w10: U1.5 4443,2672 4376,2605 4196,2605 4151,2560 4151,2410 4239,2322 4239,2114 4294,2059 4294,1843 4377,1760 4471,1760 4556,1675 4556,1505 4716,1345 4756,1345 4811,1290 SL1.7
D1_P: SL1.8 U1.4 | length 2125.6
  Top Layer w10: U1.4 4433,2692 4366,2625 4186,2625 4131,2570 4131,2399 4216,2314 4216,2105.36 4248,2073.36 4248,1990 4268,1970 4268,1828 4356,1740 4466,1740 4536,1670 4536,1500 4721,1315 4746,1315 4761,1300 SL1.8
D2_N: SL1.1 U2.32 | length 408.9
  Top Layer w10: v2(5081,1295) 5111,1265 SL1.1 ; v2(5306,1335) 5345.18,1295.82 5391.21,1295.82 U2.32
  Bottom Layer w10: v2(5081,1295) 5146,1295 5186,1335 v2(5306,1335)
D2_P: R20.2 SL1.2 U2.33 | length 851.9
  Top Layer w6: v2(5031,1290) 5066,1325 5083,1325 5147,1261 5147,1103 R20.2
  Top Layer w10: v2(5031,1290) 5036.62,1290 5061,1265.62 SL1.2 ; v2(5306,1300) 5330.21,1275.79 U2.33
  Bottom Layer w10: v2(5031,1290) 5056,1265 5156,1265 5191,1300 v2(5306,1300)
D3_N: JP2.11 JP2.12 SL1.3 | length 2900.2
  Top Layer w8: SL1.3 5011,1310 v2(5011.62,1310.62) ; v2(5269,1602) 5281,1614 6330,1614 6401,1685 6401,1736.63 6328,1809.63 6328,2445.37 6367.34,2484.71 6427.07,2484.71 6626.38,2684.02 6642.71,2684.02 6653.94,2695.25 6653.94,2719.79 6655.84,2721.69 JP2.12@6675.53,2721.69
  Bottom Layer w8: v2(5011.62,1310.62) 5011.62,1320.62 5269,1578 v2(5269,1602)
D3_P: JP2.9 JP2.10 SL1.4 | length 2910.1
  Top Layer w8: v2(5246,1625) 5253,1632 6323,1632 6386,1695 6386,1730 6310,1806 6310,2449 6361,2500 6420.73,2500 6615.57,2694.83 6615.57,2720.79 6616.47,2721.69 JP2.10@6636.16,2721.69
  Top Layer w10: SL1.4 4981,1262 v2(4981,1315)
  Bottom Layer w8: v2(4981,1315) 4981.36,1315 5246,1579.64 v2(5246,1625)
GND: C1.2 C2.1 C3.1 C4.1 C5.2 C6.1 C7.1 C8.1 C9.1 C10.1 C11.1 C12.2 C13.2 C15.2 C17.1 C18.2 C19.2 C20.1 C21.1 C22.1 C23.2 C24.1 C25.1 C26.1 C27.1 C28.1 C30.1 CY1.1 D1.1 D2.1 Fan1.2 Fan2.2 Fan3.2 FPC1.1 FPC1.12 FPC1.13 FPC1.14 J1.A2 J1.A8 J1.MP1 J1.MP2 J1.MP3 J1.MP4 J2.3 J2.4 JP1.2 JP2.1 JP2.2 JP2.3 JP2.4 JP2.5 JP2.6 JP2.7 JP2.8 JP4.2 Q1.2 Q2.2 R2.2 R5.2 R7.2 R13.2 RESET1.1 RJ1.P10 SL1.12 SWD1.1 U1.3 U2.8 U2.23 U2.35 U2.47 U3.2 U4.25 U4.29 U4.41 USBC1.1 USBC1.2 USBC1.3 USBC1.4 USBC1.A1 USBC1.A12 USBC1.B1 USBC1.B12 X3.2 X3.4 | length 1917.7
  Top Layer w10: v1(4466,2730) 4471.41,2730 4489.41,2712 U1.3 ; C3.1 4474.54,2580 4496,2580 4506,2570 v1(4506,2540) ; C7.1 C7.1@4911,926.54 ; SL1.12 C7.1@4911,926.54 ; C11.1@4974.54,783 4969.62,783 4935.09,817.52 4935.09,847.37 4929.46,853 C10.1 4919.62,853 4913.99,858.63 4913.99,863.55 4911,866.54 C7.1@4911,926.54 ; C30.1 5291,1230.79 5296.63,1236.42 U2.35 ; U2.47 5639.58,1112.79 v1(5651.79,1100.58) 5663.99,1088.38 5663.99,1065.63 5669.62,1060 C17.1 ; U2.8 5816.99,1354.53 5830.45,1367.99 5835.37,1367.99 5841,1373.62 C4.1 ; v6@5979.75,918.75 6024.36,874.15 6035.91,874.15 6045.88,864.17 U4.29 6045.88,839.65 6047.69,837.83 6047.69,793.28 6101,793.28 U4.41 ; USBC1.B12 6068.92,133.82 6068.92,162.36 6077.85,171.3 USBC1.A1 ; U4.41@6108.13,805 6108.13,912.05 6116.08,920 C27.1 C28.1 ; USBC1.B1 6284.54,145.71 6293.48,154.65 6293.48,183.19 USBC1.A12 6325.48,184.09 USBC1.2@6351.08,158.5 ; C26.1 6366.08,776.46 C25.1@6371,771.53 ; C25.1 C25.1@6371,771.53 ; v1(6416,750) 6410.59,750 6394.68,765.9 6376.63,765.9 C25.1@6371,771.53
  Top Layer w12: USBC1.1@6010.92,158.51 6036.52,132.91 USBC1.B12 ; 6298.73,89.22 6284.54,103.41 USBC1.B1 6290.44,138.82 USBC1.2@6338.48,138.82
  Top Layer w15: C23.2 5836,919 v1(5870,885)
  Top Layer w20: C12.2 C13.2
  Top Layer w25: v1(6684,1035) 6687.57,1038.57 U3.2
  other v1: 5956,-20 5825,121 4901,130 5011,130 6006,271.5 6077,276 6298.45,395.25 4864,427 6292,452 6297,510 6546,550 6488,554 6544,623 6524,678 6548,727 6497,729 5740,736 4920,752 5284,777 5358,779 5513,780 5433,781 6551,790 6494,795 4664,807 6612,822 4898.99,848 5511,865 5758,872 5953,883 6282,997 4661,1070 5586,1090 6466,1120 4661,1150 4661,1220 5276,1230 5826,1370 6741,1400 6156,1420 5516,1580 4721,1700 4651,1770 4673,1835 6496,1840 4766,1905 4827,1906 6366,1910 6456,1910 4535,1919 6806,1920 4763,1962 4825,1964 6366,2000 4596,2020 4761,2020 4824,2021 4203,2071 6806,2080 6366,2090 6456,2090 4492,2112 6626,2223 6678,2223 6723,2223 6524,2227 4411,2389 6681,2390 4656,2400 4716,2460 4286,2480 4366,2480 6596,2515 6311,2660 6491,2660 4251,2700 6309,2745 4251,2790 5286,3060 5356,3060 4456,3140 4676,3140 4601,3340 4691,3340 4601,3430 4691,3430 4836,3460 4896,3460 5266,3460 5326,3460
  other v2: 6046,700 6076,700 6126,700 6156,700 6046,730 6076,730 6126,730 6156,730 6046,770 6076,770 6126,770 6156,770 6046,800 6076,800 6126,800 6156,800
  other v4: 6596,1273
  other v6: 6321,775 6356,775 5981,920
IMU_RX: D1.2 J1.A1 R10.1 | length 749.2
  Top Layer w10: R10.1 D1.2 4521,3005.24 4570.76,3055 4774.55,3055 4876,3156.45 4876,3253.68 4900.25,3277.93 4900.25,3377.52 J1.A1
IMU_START: J1.B4 U2.26 | length 2233.6
  Top Layer w8: J1.B4 5061,3123 5048,3110 4983,3110 4871,2998 4871,1690 4966,1595 5051,1595 5232.42,1413.58 U2.26
IMU_TX: D2.2 J1.B1 R11.1 | length 475.2
  Top Layer w10: R11.1 D2.2 4780.33,2999.33 4911,3130 J1.B1
LED0: U4.32
LED2: U4.24 | length 2.5
  Top Layer w6: U4.24@6124.26,848.76 U4.24@6126,850.49
LIDAR-PPS: R8.2 R18.2 U2.45 | length 3123.6
  Top Layer w10: v2(4181,2555) 4181,2414 4267,2328 4267,2129 4349.54,2046.46 R18.2 4412.55,1782.99 4473.01,1782.99 4591,1665 4591,1500 4696,1395 5091,1395 5197,1289 5197,1162 5334,1025 5616,1025 5626,1035 5626,1100 5600.56,1125.44 5600.56,1165.21 U2.45 ; v2(4346,2735) 4346,2736.56 4348.99,2739.54 4348.99,2884.37 4354.62,2890 R8.2
  Bottom Layer w10: v2(4181,2555) 4344.9,2718.9 4344.9,2733.9 v2(4346,2735)
LIDAR-RX: R17.2 U2.42 | length 1553.3
  Top Layer w10: R17.2 4558.54,1737.46 4616,1680 4616,1505 4706,1415 5101,1415 5216,1300 5216,1175 5276,1115 5531,1115 5541.16,1125.16 U2.42
MDI0_N: RJ1.P3 T1.11 U4.2 | length 1209.1
  Top Layer w8: T1.11 5129.78,388.4 RJ1.P3 ; T1.11@5131.67,480 5131.67,545.67 5266,680 5824,680 5890,614 6045.88,614 U4.2
MDI0_P: RJ1.P2 T1.12 U4.1 | length 1315.4
  Top Layer w8: RJ1.P2 5090.41,278.89 T1.12 ; T1.12@5092.3,480 5092.3,536.3 5259,703 5823,703 5893,633 6030.13,633 U4.1
MDI1_N: RJ1.P7 T1.8 U4.5 | length 1207.2
  Top Layer w8: T1.8 5247.89,470.29 RJ1.P7 ; T1.8@5249.78,480 5249.78,553.78 5333,637 5813,637 5886,564 6085,564 6093.13,572.13 U4.5
MDI1_P: RJ1.P4 T1.9 U4.4 | length 1295
  Top Layer w8: RJ1.P4 5189.96,276.38 5189.96,409.96 5208.52,428.52 T1.9 ; T1.9@5210.41,480 5210.41,545.59 5322.82,658 5820,658 5897,581 6077.38,581 U4.4
MDI2_N: RJ1.P6 T1.5 U4.7 | length 1269.9
  Top Layer w8: RJ1.P6 5331.52,320 5380.38,320 5402,341.62 5402,395.38 5366,431.38 T1.5 ; T1.5@5367.89,480 5367.89,551.89 5407,591 5809,591 5870,530 6097,530 6124.62,557.62 U4.7
MDI2_P: RJ1.P5 T1.6 U4.6 | length 1324.5
  Top Layer w8: RJ1.P5 5262.62,376.38 5306,333 5375,333 5389,347 5389,390 5326.63,452.37 T1.6 ; T1.6@5328.52,480 5328.52,542.52 5398,612 5813,612 5879,546 6092,546 6108.87,562.87 U4.6
MDI3_N: RJ1.P8 T1.2 U4.10 | length 1170.3
  Top Layer w8: RJ1.P8 5410.38,276.38 5493,359 5493,471.11 T1.2@5486,478.11 ; T1.2 T1.2@5486,478.11 ; T1.2@5486,470 T1.2@5486,478.11 ; U4.10 6171.87,629.13 6186,615 6186,570 6115,499 5845,499 5794,550 5506,550 5486,530 T1.2@5486,478.11
MDI3_P: RJ1.P9 T1.3 U4.9 | length 1030.3
  Top Layer w8: RJ1.P9 5441.8,477.06 T1.3 ; T1.3@5446.63,480 5446.63,539.37 5446,540 5475,569 5801,569 5855,515 6108,515 6171,578 6171,604.96 6156.12,619.84 U4.9
NetC9_2: C9.2 U3.4 | length 90.5
  Top Layer w20: U3.4 6723,1264.54 C9.2
NetC10_2: C10.2 SL1.13 | length 158.2
  Top Layer w10: SL1.13 4961,858.63 4966.63,853 C10.2
NetC11_2: C11.2 SL1.14 | length 227.7
  Top Layer w12: SL1.14 5013.22,1005.77 5013.22,787.23 C11.2@5017.46,783
NetC14_2: C14.2 USBC1.B2 | length 902.2
  Top Layer w8: v2(6255,291) 6224,291 6119,396 6119,451 6225,557 6361,557 6396,592 6396,641.46 6379.01,658.45 6379.01,663.37 6372.38,670 C14.2 ; USBC1.B2 6265.43,132.34 6265.43,95.26 v2(6266,94.69)
  Bottom Layer w8: v2(6255,291) 6255,105.69 6264,96.69 v2(6266,94.69)
NetC16_2: C16.2 USBC1.B3 | length 877
  Top Layer w8: v2(6230,266) 6213,266 6095,384 6095,456 6214,575 6328.45,575 6367.46,614.01 C16.2 C16.2@6369.96,612.5 ; USBC1.B3 6245.59,132.5 6245.59,70.1 v2(6246,69.69)
  Bottom Layer w8: v2(6230,266) 6230,95.69 6241,84.69 6236,79.69 v2(6246,69.69) v2@6246,64.69
NetC19_1: C19.1 RJ1.P1 T1.1 T1.4 T1.7 T1.10 | length 911.3
  Top Layer w12: C19.1 5002,496 v4(5035,529) ; v4(5167,529) 5169.15,526.85 T1.10 ; v4(5287,531) 5287.26,530.74 T1.7 ; v4(5405,529) 5405.37,528.63 T1.4 ; v4(5522,529) 5523.48,527.52 T1.1
  Bottom Layer w12: RJ1.P1 5037.37,526.63 v4(5035,529) v4(5167,529) v4(5405,529) v4(5522,529)
NetCY1_2: CY1.2 R6.1 R12.1 R14.1 R19.1 | length 1175.7
  Top Layer w12: R6.1@4858.59,299 R6.1 R12.1 4959.41,300.59 5047,213 5511.59,213 5532,192.59 R14.1 5780.41,192.59 5794.09,178.91 CY1.2
NetJ1_B2: J1.B2 R8.1 | length 680.3
  Top Layer w10: R8.1@4416,2890 4711,2890 4950.25,3129.25 4950.25,3160.98 J1.B2
NetJ2_1: J2.1 Q1.3 R15.1 | length 506.4
  Top Layer w10: J2.1 4351.01,2310.42 4409.43,2252 4487,2252 4506.46,2232.54 R15.1 4643,2058.46 Q1.3
NetJ2_2: J2.2 Q2.3 R16.1 | length 409.9
  Top Layer w10: J2.2 4301.01,2310.42 4312.54,2321.95 R16.1 4312.54,2147.46 Q2.3@4448,2012
NetJP3_1: JP3.1 T1.13 | length 126.5
  Top Layer w12: T1.13 5090.41,60.59 5125.72,25.28 JP3.1@5125.72,0
NetJP3_2: JP3.2 T1.14 | length 130.6
  Top Layer w12: T1.14 5129.78,71.22 5174.94,26.06 JP3.2@5174.94,0
NetJP3_3: JP3.3 T1.16 | length 120.5
  Top Layer w12: T1.16 5206,109.37 5206,60 5224.15,41.85 JP3.3@5224.15,0
NetJP3_4: JP3.4 T1.17 | length 122.4
  Top Layer w12: T1.17 5247.89,68.11 5273.36,42.64 JP3.4@5273.36,0
NetJP3_5: JP3.5 T1.19 | length 113.6
  Top Layer w12: JP3.5@5322.57,0 5322.57,51.57 5326,55 5326,111.26 T1.19
NetJP3_6: JP3.6 T1.20 | length 114.3
  Top Layer w12: T1.20 5371.79,106.1 JP3.6@5371.79,0
NetJP3_7: JP3.7 T1.22 | length 121.7
  Top Layer w12: JP3.7@5421,0 5421,40 5444.74,63.74 T1.22
NetJP3_8: JP3.8 T1.23 | length 119.2
  Top Layer w12: JP3.8@5470.21,0 5470.21,39.21 5486,55 5486,110 T1.23
NetPC1_K: PC1.2 R3.1 | length 73.7
  Top Layer w12: R3.1 6437.46,947.02 PC1.2
NetPOW1_K: POW1.2 R2.1 | length 144.4
  Top Layer w12: R2.1 6407.46,855 POW1.2
NetQ1_1: Q1.1 R17.1 | length 79.7
  Top Layer w10: R17.1 4601.46,1903.86 Q1.1
NetQ2_1: Q2.1 R18.1 | length 72.3
  Top Layer w12: R18.1 4407.6,1861.14 Q2.1
NetR4_1: R4.1 U1.9 | length 83.2
  Top Layer w10: R4.1 4601,2511 U1.9
NetR6_2: R6.2 T1.15 | length 405.7
  Top Layer w12: R6.2 4857,224 4885.59,195.41 4935.59,195.41 4974,157 5161.04,157 5169.15,148.89 T1.15
NetR7_1: R7.1 U1.11 | length 89.5
  Top Layer w6: U1.11 4640,2530.92 4658,2512.92 R7.1
NetR10_2: R10.2 U1.26 | length 156.4
  Top Layer w10: R10.2 4526,2855.69 4526,2830 4531,2825 4614.14,2825 4620,2819.14 U1.26
NetR11_2: R11.2 U1.25 | length 79.4
  Top Layer w10: R11.2 4612.13,2860.69 4640,2832.82 U1.25
NetR12_2: R12.2 T1.18 | length 447.8
  Top Layer w10: R12.2@4926,250.41 4996.41,180 5269,180 5287.26,161.74 T1.18
NetR13_1: R13.1 U4.38 | length 125.4
  Top Layer w6: R13.1 5887.97,708.38 5947.58,708.38 5949.83,710.63 U4.38
NetR14_2: R14.2 T1.21 | length 300.7
  Top Layer w12: T1.21 5406,112.52 5406,152 5415,161 5640,161 R14.2@5656,145
NetR19_2: R19.2 T1.24 | length 263.2
  Top Layer w12: T1.24 5526,114.41 5619.59,114.41 5642,92 5713.58,92 R19.2
NetSL1_15: SL1.15 X1.2 | length 698.1
  Top Layer w12: X1.2 4728.99,716 5033,716 5061,744 SL1.15
NetSL1_16: SL1.16 X1.1 | length 378.4
  Top Layer w12: SL1.16 5111,631.06 X1.1@5112.06,630
OSCIN: C15.1 R9.2 U2.5 X2.2 | length 1031.3
  Top Layer w10: U2.5 5828.53,1295.47 5963,1161 5963,1118 5991,1090 6081,1090 6101.43,1110.43 R9.2 6101.43,1148.94 6220.58,1268.08 6220.58,1268.51 6243.01,1290.95 ; C15.1@6237.46,1430 C15.1 6243.01,1424.45 6243.01,1290.95 ; C15.1@6242.38,1430 C15.1@6248.01,1424.37 ; X2.2 6248.06,1296 6243.01,1290.95
OSCOUT: C18.1 R9.1 U2.6 X2.1 | length 651.9
  Top Layer w10: U2.6 6044.78,1315.16 X2.1@6059.94,1300 ; R9.1@6030.57,1145 6035.41,1149.84 6035.41,1275.47 X2.1@6059.94,1300 ; C18.1 6069.54,1309.6 X2.1@6059.94,1300
PA0: FPC1.10 U2.10 | length 1320.8
  Top Layer w8: U2.10 5764.9,1393.9 5861,1490 6506,1490 6694.85,1678.85 FPC1.10
PA1: FPC1.9 U2.11 | length 1291.8
  Top Layer w8: U2.11 5764.58,1413.58 5856,1505 6499.38,1505 6675.15,1680.77 FPC1.9
PA2: FPC1.8 U2.12 | length 1261.8
  Top Layer w8: U2.12 5764.27,1433.27 5851,1520 6491,1520 6655.5,1684.5 FPC1.8
PA3: FPC1.7 U2.13 | length 1269
  Top Layer w8: U2.13 5659.82,1485 5721,1485 5771,1535 6481,1535 6635.85,1689.85 FPC1.7
PA4: FPC1.6 U2.14 | length 1291.8
  Top Layer w8: U2.14 5640.31,1485.18 5640.31,1529.31 5661,1550 6471,1550 6616.15,1695.15 FPC1.6
PA5: FPC1.5 U2.15 | length 1287.9
  Top Layer w8: U2.15 5620.63,1485.18 5620.63,1528.01 5657.62,1565 6461,1565 6596.45,1700.45 FPC1.5
PA6: FPC1.4 U2.16 | length 1292.5
  Top Layer w8: U2.16 5599.48,1485.18 5599.48,1530.14 5599.31,1530.31 5599.31,1538.31 5641,1580 6451,1580 6576.75,1705.75 FPC1.4
PA7: FPC1.3 U2.17 | length 1294.7
  Top Layer w8: U2.17 5580.53,1544.53 5631,1595 6446,1595 6557.05,1706.05 FPC1.3
PC13: R3.2 U2.2 | length 796
  Top Layer w8: U2.2 5789.58,1236.42 5811,1215 5811,1177 5948,1040 6369.62,1040 6389.62,1020 R3.2
PC14: C12.1 U2.3 Y1.1 | length 814.8
  Top Layer w8: U2.3 5800.9,1256.1 5831,1226 5831,1184 5960,1055 6146.98,1055 6186.98,1095 6351.99,1095 6366.99,1080 C12.1
PC15: C13.1 U2.4 Y1.0 | length 825.9
  Top Layer w10: U2.4 5812.21,1275.79 5851,1237 5851,1197 5978,1070 6116.98,1070 6186.98,1140 6379.62,1140 6389.62,1150 C13.1
RESET: C2.2 R1.1 RESET1.2 U2.7 | length 2339.6
  Top Layer w8: U2.7 5845.84,1334.84 5961,1450 6561,1450 6732,1621 6732,1719 6910,1897 6910,2153 6952,2195 6952,2328 6938,2342 6862,2342 ; C2.2 6816.36,2300.36 6823,2307 ; R1.1@6856.54,2307 6862,2312.46 6862,2342 ; RESET1.2 6862,2413 6862,2342
  Top Layer w12: 6823,2307 R1.1@6856.54,2307
SSRX_N: U4.15 USBC1.A10 | length 1001.5
  Top Layer w5: U4.15 6239.95,742.13 6277.69,779.87 6277.69,798.31 6289.45,810.08 6392.92,810.08 6445,758 6445,551.85 6407,513.85 6407,291 6356,240 6283,240 6255.02,212.02 USBC1.A10
SSRX_P: U4.16 USBC1.A11 | length 1018.5
  Top Layer w6: U4.16 6240.84,757.87 6264.52,781.55 6264.52,800 6285.52,821 6399,821 6461,759 6461,553 6419,511 6419,287 6362,230 6360.85,230 6360.35,229.5 6289.5,229.5 6274.7,214.7 USBC1.A11
SSTX_N: C16.1 U4.12 | length 164.3
  Top Layer w6: U4.12 6226,694.88 6241,679.88 v2@6241,675 ; v2(6271,640) 6286,640 6316,610 C16.1
  Bottom Layer w6: v2(6238.5,671.81) 6239.19,671.81 v2(6271,640)
SSTX_P: C14.1 U4.13 | length 149
  Top Layer w6: U4.13 6245.37,710.63 v2(6251,705) ; v2(6286,665) 6291,670 C14.1
  Bottom Layer w6: v2(6251,705) 6251,700 v2(6286,665)
SWDCLK: SWD1.2 U2.37 | length 948
  Top Layer w8: SWD1.2@4776,1525 4776,1455 4791,1440 5106,1440 5236,1310 5236,1183 5274,1145 5381,1145 5401.55,1165.55 U2.37
SWDIO: SWD1.3 U2.34 | length 659.2
  Top Layer w8: SWD1.3@4876,1525 4876,1470 4886,1460 5111,1460 5314.9,1256.1 U2.34
U2DM: SL1.5 U4.17 | length 1932.1
  Top Layer w8: SL1.5 4911,1340 4941,1370 5088,1370 5179,1279 5179,1154 5333,1000 5921,1000 5946,1025 6161,1025 6252.52,933.48 6252.52,786.52 6239.62,773.62 U4.17
U2DP: SL1.6 U4.18 | length 2026.6
  Top Layer w8: SL1.6 4863.99,1239.01 4863.99,1196.7 4875.69,1185 4921,1185 4936,1200 4936,1335 4951,1350 5083,1350 5162,1271 5162,1145 5332,975 5914.38,975 5949.38,1010 6157.62,1010 6239.52,928.09 6239.52,796.52 6232.37,789.37 U4.18
USB3-D_N: SL1.9 USBC1.A7 USBC1.B7 | length 2097.4
  Top Layer w8: SL1.9 4761,880 v2(4841,800) ; USBC1.B7 6168.34,131.01 6168.34,107.35 v2(6181,94.69) ; v2(6186,224.69) 6195.89,214.8 6195.89,184.16 USBC1.A7
  Bottom Layer w8: v2(4841,800) 5101,800 5318,583 5912,583 6189,306 6189,227.69 v2(6186,224.69) 6186,101.78 6181,96.78 v2(6181,94.69)
USB3-D_P: SL1.10 USBC1.A6 USBC1.B6 | length 1933.9
  Top Layer w8: SL1.10 4811,870 4876,805 v2(4876,775) ; v2(6171,249.69) 6166,244.69 6166,219.69 6176,209.69 6176,184.37 USBC1.A6 6178.19,182.19 6178.19,164.53 6184.21,158.51 6184.21,134.82 USBC1.B6
  Bottom Layer w8: v2(4876,775) 4886,785 5096,785 5315,566 5899,566 6171,294 v2(6171,249.69)
VCC: C20.2 Fan1.1 Fan2.1 Fan3.1 JP1.1 JP4.1 USBC1.A4 USBC1.A9 USBC1.B4 USBC1.B9 | length 5096.3
  Top Layer w8: USBC1.A4 6135,182.19 6135,164.54 6128.97,158.51 6128.97,134.82 USBC1.B9 6127.06,88.63 6151,64.69 6201,64.69 6225.49,89.18 USBC1.B4 6227.4,134.82 6227.4,158.51 6233.42,164.53 6233.42,182.19 USBC1.A9 6235.33,225.33 6274,264 6346,264 6370.15,288.15 JP4.1
  Top Layer w12: C20.2 5935,180.09 5992.91,238 6103.48,238 6137.74,203.74
  Top Layer w20: C20.2 6028.09,67 6105.43,67 6127.06,88.63
  Top Layer w30: v3@6485,3155 6486.15,3156.15 Fan3.1 ; Fan1.1 v3(6563.65,2855.35) v3@6564,2855 ; Fan2.1 v3(6888.5,2816)
  Top Layer w50: JP1.1 5915,207 C20.2 ; v3@6368,499 v3(6370.15,496.85) JP4.1
  Bottom Layer w30: v3(6370,378) 6447.07,455.07 6590.93,455.07 6590.93,481 6598,481 6598.24,482.03 6604.06,506.78 6609.88,531.53 6615.69,556.27 6621.5,581.02 6627.09,604.82 6627.42,606.22 6623.69,602.49 6968.06,2040.27 6984.42,2050.31 6984.42,2718.58 6858,2845 6574,2845 v3(6563.65,2855.35) 6486,2933 6486,3146 v3@6485,3147
  other v3: 6370,432 6484,3147
XTALI: C23.1 U4.35 X3.1 | length 482.2
  Top Layer w8: C23.1@5767,918 5802,883 5824,883 5949.87,757.13 6001.85,757.13 U4.35
  Top Layer w10: X3.1 5625.5,899.5 5658,932 5754.54,932 C23.1
XTALO: C24.2 U4.36 X3.3 | length 373.7
  Top Layer w6: 5825.5,763.5 5846.87,742.13 U4.36
  Top Layer w10: X3.3 5705.19,779 5810,779 ; C24.2 5811.46,777.54 5825.5,763.5
pads on no net: Fan1.0 Fan2.0 Fan3.0 J1.A3 J1.A4 J1.A5 J1.A6 J1.A7 J1.B3 J1.B5 J1.B6 J1.B7 J1.MH1 J1.MH2 JP2.0 JP3.0 JP4.0 U1.1 U1.2 U1.10 U1.12 U1.13 U1.14 U1.15 U1.16 U1.17 U1.18 U1.19 U1.20 U1.21 U1.22 U1.23 U1.24 U1.27 U1.28 U1.29 U2.18 U2.19 U2.21 U2.22 U2.25 U2.27 U2.28 U2.29 U2.30 U2.31 U2.38 U2.39 U2.40 U2.41 U2.43 U2.46 U4.28 U4.30 U4.31 USBC1. USBC1.A2 USBC1.A3 USBC1.B10 USBC1.B11

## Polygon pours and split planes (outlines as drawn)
GND on Top Layer "GND_L02_P-001" (solid, remove dead copper, pour order 0): 7353.02,3808.42 7353.02,-47 7360.02,-54 7347.02,-67 3889.02,-67 3889.02,3017 4726.52,3854.5
GND on Bottom Layer "GND_L02_P-001" (solid, remove dead copper, pour order 2): 3949,3860.42 3949,-59 7322,-59 7509,-246 7512,-243 7512,3833.44

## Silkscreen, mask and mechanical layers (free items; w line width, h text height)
Top Overlay:
  text "Stereye-0517" at 5166,840 h78.74
Bottom Overlay:
  text "B-" at 5354,46 h80 r90
  text "B+" at 5410,46 h80 r90
  text "D+" at 5184,43 h80 r90
  text "D-" at 5128,42 h80 r90
  text "C+" at 5298,41 h80 r90
  text "C-" at 5241,39 h80 r90
  text "A-" at 5466,39 h80 r90
  text "A+" at 5517,37 h80 r90
Top Solder:
  drawing of 1778 lines, arcs and shapes, not listed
